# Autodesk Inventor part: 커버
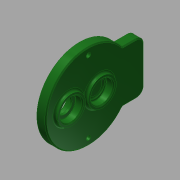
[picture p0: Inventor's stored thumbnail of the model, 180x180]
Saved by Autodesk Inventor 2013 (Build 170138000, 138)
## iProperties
Created: 2016-02
Part Number: 커버
Material: 일반
Document SubType Name: Modeling
Designer: mduedu
Density: 2.71 g/cm^3
Author: mduedu
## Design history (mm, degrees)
sketch "스케치1"
  geometry: C1 r 43 at (0, 0); 1 further point
  constraints: 1 centre point, 1 coincident
  dimensions: "d0" = 86 diameter of C1
extrude "돌출1" new body sketch "스케치1" distance "d1" = 9; taper "d2" = 0 deg
sketch "스케치2"
  geometry: C1 r 14 at (0, 11); 1 further point
  constraints: 1 centre point, 1 vertical alignment
  dimensions: "d3" = 28 diameter of C1; "d6" = 11 distance of C1.centre point (0, 0)
extrude "돌출2" join sketch "스케치2" distance "d7" = 3; taper "d8" = 0 deg
sketch "스케치3"
  geometry: C1 r 14 at (0, -20); 1 further point
  constraints: 1 centre point, 1 vertical alignment
  dimensions: "d9" = 28 diameter of C1; "d10" = 20 distance of C1.centre point (0, 0)
extrude "돌출3" join sketch "스케치3" distance "d11" = 3; taper "d12" = 0 deg
hole "구멍1" diameter "d15" = 22; stored, may be unused: countersink angle "d19" = 90 deg, drill point angle "d21" = 0 deg; dims "d13" = 10, "d14" = 10, "d16" = 6, "d17" = 4, "d18" = 2, "d20" = 7
hole "구멍2" diameter "d24" = 18; stored, may be unused: countersink angle "d28" = 90 deg, drill point angle "d30" = 0 deg; dims "d22" = 10, "d23" = 10, "d25" = 6, "d26" = 4, "d27" = 2, "d29" = 1
hole "구멍3" diameter "d33" = 22; stored, may be unused: countersink angle "d37" = 90 deg, drill point angle "d39" = 0 deg; dims "d34" = 6, "d35" = 4, "d36" = 2, "d38" = 7, "d73" = 10, "d74" = 10
sketch "스케치7"
  geometry: L1 (-26, 34.249)-(26, 34.249); L2 (26, 34.249)-(26, 56); L3 (26, 56)-(-26, 56); L4 (-26, 56)-(-26, 34.249); A1 r 43 centre (0, 0) between (-26, 34.249) and (26, 34.249) reference; 1 further point
  constraints: 8 end point, 2 parallel, 2 point on circle, 1 horizontal, 1 perpendicular
  dimensions: "d95" = 52 distance of L2.end L3.end; "d97" = 56 distance from line of L3 point (0, 0)
extrude "돌출5" join sketch "스케치7" stored distance "d98" = 10; taper "d99" = 0 deg
sketch "스케치4"
  geometry: C1 r 14 at (0, -20) reference; C2 r 18 at (0, -20); 1 further point
  constraints: 1 centre point, 1 coincident
  dimensions: "d40" = 36 diameter of C2
extrude "돌출4" join sketch "스케치4" distance "d41" = 4; taper "d42" = 0 deg
hole "구멍4" diameter "d45" = 22; stored, may be unused: countersink angle "d49" = 90 deg, drill point angle "d51" = 0 deg; dims "d43" = 10, "d44" = 10, "d46" = 6, "d47" = 4, "d48" = 2, "d50" = 7
hole "구멍5" diameter "d54" = 15; stored, may be unused: countersink angle "d58" = 90 deg, drill point angle "d60" = 0 deg; dims "d52" = 10, "d53" = 10, "d55" = 6, "d56" = 4, "d57" = 2, "d59" = 7
fillet "모깎기1" dims "d61" = 0.3
fillet "모깎기2" dims "d62" = 2
chamfer "모따기1" distance "d63" = 1; stored, may be unused: second distance "d64" = 2, angle "d65" = 45 deg
fillet "모깎기6" dims "d88" = 2
sketch "스케치5" dims "d67" = 72
  geometry: 4 further points
  constraints: 2 horizontal alignment, 1 coincident, 5 other
  dimensions: "d71" = 360 deg dimension on point (0, 0) point (-36, 0) (derived)
fillet "모깎기4" dims "d75" = 2
sketch "스케치6"
  geometry: 2 further points
hole "구멍6" sketch "스케치6" at (36, 0), (-36, 0) diameter "d76" = 4.5; stored, may be unused: countersink angle "d80" = 90 deg, drill point angle "d82" = 0 deg; dims "d77" = 6, "d78" = 8, "d79" = 4.6, "d81" = 8
fillet "모깎기7" dims "d100" = 8, "d101" = 2
chamfer "모따기2" distance "d90" = 1; stored, may be unused: second distance "d91" = 2, angle "d92" = 45 deg
node "솔리드1"
node "절단 모서리 투영1"
